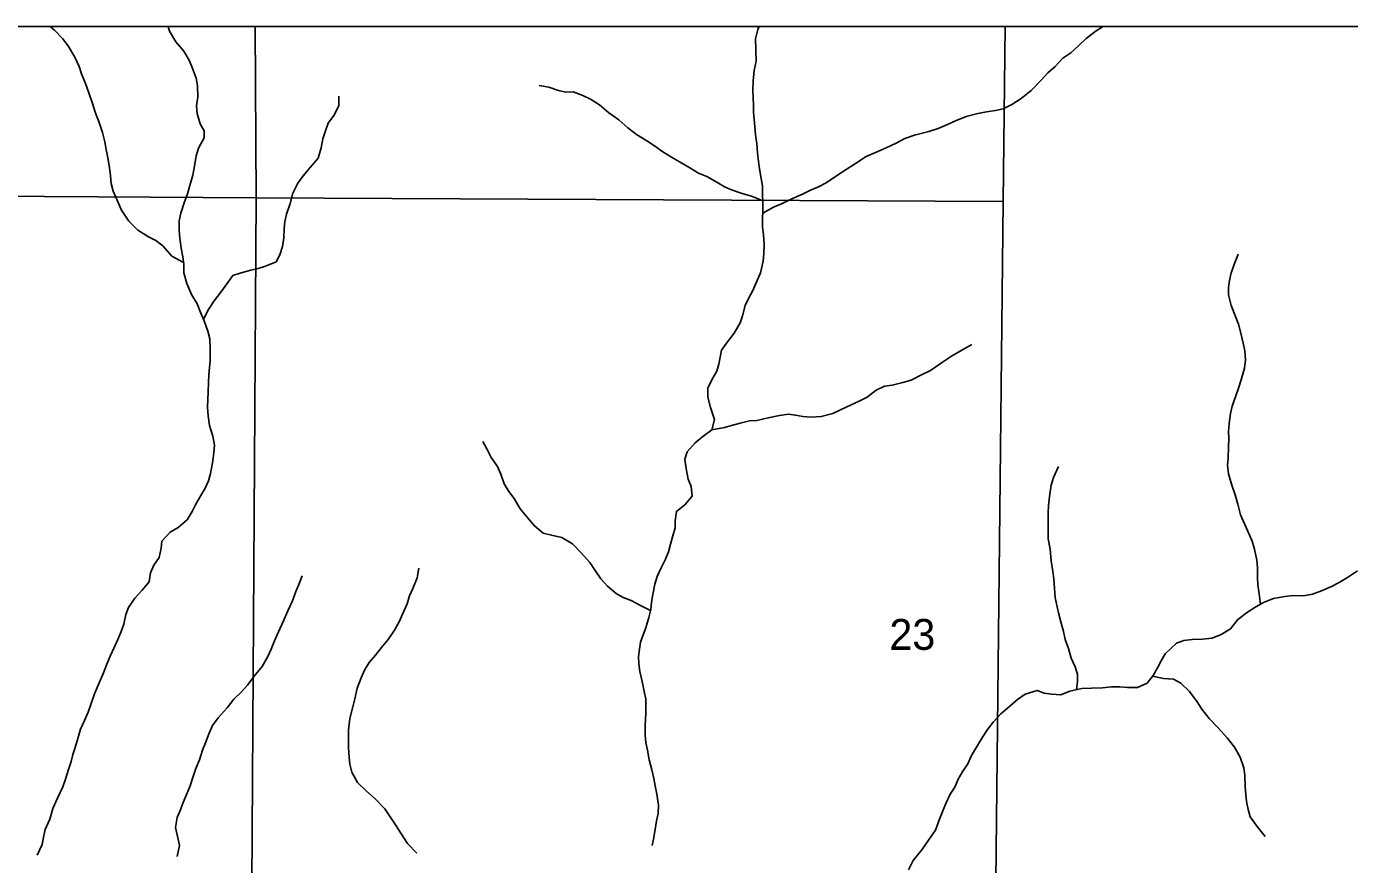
# Model space of a CAD drawing. Extents: x -10 to 158, y 8 to 33.
# Drawn here: x -6.322 to -4.528, y 13.985 to 15.122 of the extents above; entities that cross this region are included whole.
import ezdxf

# ---------------------------------------------------------------- set-up
doc = ezdxf.new("R2010")
doc.units = 0
for name, color, linetype in [('GM_X_Corporation', 7, 'Continuous'), ('GM_X_Minor_River', 7, 'Continuous'), ('GM_X_Section_Text', 7, 'Continuous')]:
    doc.layers.add(name, color=color, linetype=linetype)

msp = doc.modelspace()

# ---------------------------------------------------------------- linework, layer by layer
at = {"layer": 'GM_X_Corporation'}
for points in [[(-4.0034, 12.5894), (-3.9988, 12.8693), (-3.9975, 12.9799), (-3.993, 13.4391), (-3.9918, 13.5028), (-3.9936, 13.8697), (-3.9863, 14.2697), (-3.983, 14.8658), (-3.9828, 14.8868), (-3.9824, 15.1217), (-9.5644, 15.1217)], [(-4.0034, 12.5894), (-3.9988, 12.8693), (-3.9975, 12.9799), (-3.993, 13.4391), (-3.9918, 13.5028), (-3.9936, 13.8697), (-3.9863, 14.2697), (-3.983, 14.8658), (-3.9828, 14.8868), (-3.9824, 15.1217), (-7.9061, 15.1217)]]:
    msp.add_lwpolyline(points, dxfattribs=at)
for points in [[(-6.0117, 15.1217), (-7.016, 15.1217), (-7.0152, 14.8959), (-6.0105, 14.8894)], [(-4.9947, 15.1217), (-6.0117, 15.1217), (-6.0105, 14.8894), (-4.9975, 14.8842)], [(-7.0152, 14.8959), (-6.0105, 14.8894), (-6.0166, 13.8862), (-7.016, 13.8932)], [(-6.0105, 14.8894), (-4.9975, 14.8842), (-5.0085, 13.879), (-6.0166, 13.8862)]]:
    msp.add_lwpolyline(points, close=True, dxfattribs=at)
at = {"layer": 'GM_X_Minor_River'}
for points in [[(-6.3072, 13.9983), (-6.3006, 14.0124), (-6.2988, 14.0226), (-6.2962, 14.0329), (-6.2902, 14.0469), (-6.2858, 14.0614), (-6.2795, 14.0755), (-6.2724, 14.0907), (-6.2687, 14.1013), (-6.2653, 14.1127), (-6.2613, 14.1253), (-6.259, 14.1348), (-6.2557, 14.1443), (-6.252, 14.1564), (-6.2483, 14.169), (-6.2431, 14.1808), (-6.2383, 14.1922), (-6.2342, 14.2036), (-6.2297, 14.2169), (-6.223, 14.2317), (-6.2171, 14.2454), (-6.2126, 14.2572), (-6.2081, 14.2679), (-6.2022, 14.2804), (-6.1977, 14.2907), (-6.1932, 14.3013), (-6.1899, 14.3112), (-6.187, 14.3242), (-6.1832, 14.334), (-6.1746, 14.3466), (-6.1649, 14.3573), (-6.1555, 14.3687), (-6.1537, 14.3809), (-6.1492, 14.3912), (-6.1417, 14.4015), (-6.1391, 14.4144), (-6.1381, 14.4239), (-6.1268, 14.4361), (-6.1159, 14.4426), (-6.1038, 14.4529), (-6.0971, 14.4643), (-6.0923, 14.4739), (-6.0851, 14.4857), (-6.0795, 14.4956), (-6.0747, 14.5058), (-6.0721, 14.5157), (-6.0696, 14.5301), (-6.0678, 14.5434), (-6.0667, 14.5541), (-6.0691, 14.5662), (-6.0737, 14.5806), (-6.0753, 14.5938), (-6.0761, 14.6056), (-6.0758, 14.6159), (-6.0755, 14.6265), (-6.0749, 14.639), (-6.0746, 14.6489), (-6.0735, 14.6591), (-6.0728, 14.669), (-6.0725, 14.6838), (-6.073, 14.6982), (-6.0757, 14.7088), (-6.0807, 14.7224), (-6.0854, 14.733), (-6.0904, 14.7455), (-6.098, 14.7584), (-6.1042, 14.7731), (-6.1084, 14.7875), (-6.1085, 14.7993), (-6.1097, 14.8095), (-6.1121, 14.8213), (-6.1137, 14.8345), (-6.1145, 14.8452), (-6.1146, 14.8581), (-6.1124, 14.8687), (-6.108, 14.8828), (-6.1035, 14.8949), (-6.1002, 14.906), (-6.0961, 14.92), (-6.0936, 14.9348), (-6.0918, 14.9462), (-6.0884, 14.9569), (-6.081, 14.9706), (-6.0807, 14.9801), (-6.086, 14.9899), (-6.0903, 15.0039), (-6.0911, 15.0142), (-6.0893, 15.0259), (-6.0898, 15.0419), (-6.0917, 15.0517), (-6.0971, 15.0661), (-6.101, 15.0759), (-6.1083, 15.0884), (-6.119, 15.1009), (-6.1278, 15.1152), (-6.1294, 15.1217)], [(-6.1088, 14.8016), (-6.1245, 14.8102), (-6.1367, 14.8241), (-6.1462, 14.8317), (-6.1565, 14.8365), (-6.1709, 14.8456), (-6.1831, 14.8576), (-6.1931, 14.8727), (-6.1977, 14.8841), (-6.2042, 14.8985), (-6.2069, 14.9087), (-6.2078, 14.9193), (-6.209, 14.9307), (-6.2113, 14.9436), (-6.2137, 14.9549), (-6.2157, 14.9655), (-6.2188, 14.978), (-6.223, 14.9917), (-6.2284, 15.0057), (-6.2323, 15.0174), (-6.2369, 15.0303), (-6.2416, 15.0443), (-6.247, 15.0576), (-6.2504, 15.0674), (-6.2562, 15.0803), (-6.2646, 15.0946), (-6.2723, 15.1048), (-6.2837, 15.1165), (-6.2896, 15.1217)], [(-5.4735, 14.0113), (-5.4714, 14.0199), (-5.4692, 14.0328), (-5.4674, 14.0446), (-5.4652, 14.0548), (-5.4646, 14.0658), (-5.4669, 14.0806), (-5.4693, 14.092), (-5.4709, 14.1022), (-5.474, 14.114), (-5.4775, 14.1272), (-5.4798, 14.1405), (-5.4818, 14.1511), (-5.483, 14.1609), (-5.4827, 14.1738), (-5.4821, 14.1905), (-5.4818, 14.2), (-5.4818, 14.2103), (-5.4842, 14.2201), (-5.4869, 14.2334), (-5.49, 14.247), (-5.4913, 14.2576), (-5.4921, 14.2675), (-5.4906, 14.2774), (-5.4892, 14.2869), (-5.4855, 14.2967), (-5.4818, 14.3062), (-5.4781, 14.3203), (-5.4751, 14.3313), (-5.4741, 14.3412), (-5.4726, 14.3515), (-5.4697, 14.3655), (-5.4664, 14.3758), (-5.4623, 14.3857), (-5.4552, 14.3994), (-5.4514, 14.4096), (-5.4485, 14.4199), (-5.4452, 14.4313), (-5.4422, 14.4419), (-5.4423, 14.4514), (-5.4405, 14.4643), (-5.4292, 14.4731), (-5.4191, 14.485), (-5.4207, 14.4982), (-5.4245, 14.5081), (-5.4273, 14.5225), (-5.4289, 14.535), (-5.4259, 14.5452), (-5.415, 14.5571), (-5.4049, 14.5659), (-5.3924, 14.575), (-5.3887, 14.5887), (-5.3942, 14.605), (-5.398, 14.619), (-5.3981, 14.6312), (-5.3922, 14.6437), (-5.3858, 14.6544), (-5.3828, 14.6639), (-5.3792, 14.6829), (-5.3728, 14.6924), (-5.3623, 14.7061), (-5.3541, 14.7198), (-5.3507, 14.7294), (-5.3471, 14.7434), (-5.3426, 14.7529), (-5.3374, 14.7628), (-5.3325, 14.7742), (-5.3266, 14.7879), (-5.3229, 14.8035), (-5.3218, 14.8138), (-5.3215, 14.8259), (-5.3224, 14.8392), (-5.3236, 14.8502), (-5.3237, 14.8608), (-5.3234, 14.8714), (-5.3236, 14.9056), (-5.3256, 14.9158), (-5.3279, 14.9287), (-5.3291, 14.9386), (-5.3307, 14.9503), (-5.3316, 14.9625), (-5.3335, 14.9753), (-5.3344, 14.9856), (-5.3352, 14.9954), (-5.336, 15.0057), (-5.3361, 15.0152), (-5.3365, 15.0254), (-5.337, 15.0353), (-5.3363, 15.0482), (-5.3349, 15.0622), (-5.3323, 15.0748), (-5.3333, 15.1051), (-5.33, 15.1177), (-5.3282, 15.1217)], [(-5.3234, 14.8688), (-5.309, 14.8768), (-5.2969, 14.8819), (-5.283, 14.8884), (-5.2694, 14.8942), (-5.2585, 14.8996), (-5.2479, 14.9042), (-5.2373, 14.9096), (-5.226, 14.9172), (-5.2102, 14.9276), (-5.1989, 14.9352), (-5.1831, 14.9452), (-5.1706, 14.951), (-5.1563, 14.9571), (-5.1427, 14.9637), (-5.1307, 14.9698), (-5.1178, 14.9744), (-5.0982, 14.9795), (-5.0857, 14.9834), (-5.0729, 14.9888), (-5.0619, 14.9938), (-5.0476, 14.9996), (-5.0317, 15.0038), (-5.02, 15.0058), (-5.0079, 15.0078), (-4.9977, 15.0101), (-4.9856, 15.0159), (-4.9732, 15.0239), (-4.9593, 15.035), (-4.9458, 15.0488), (-4.9367, 15.0587), (-4.927, 15.0675), (-4.9168, 15.0786), (-4.9059, 15.0858), (-4.895, 15.0961), (-4.8848, 15.1053), (-4.8713, 15.1157), (-4.862, 15.1217)], [(-5.3235, 14.8851), (-5.3375, 14.8911), (-5.3515, 14.8952), (-5.3656, 14.9), (-5.3751, 14.9045), (-5.3857, 14.9105), (-5.3994, 14.9184), (-5.4104, 14.9229), (-5.4225, 14.93), (-5.4362, 14.9383), (-5.4472, 14.9443), (-5.459, 14.9518), (-5.4701, 14.9597), (-5.4807, 14.9668), (-5.4944, 14.9751), (-5.5062, 14.9841), (-5.5187, 14.995), (-5.5321, 15.0044), (-5.5446, 15.0154), (-5.5572, 15.0233), (-5.5674, 15.0281), (-5.5803, 15.033), (-5.5905, 15.0325), (-5.6004, 15.0351), (-5.6133, 15.0396), (-5.6266, 15.0418)], [(-6.0819, 14.725), (-6.0748, 14.738), (-6.0673, 14.7495), (-6.0583, 14.7613), (-6.0489, 14.7746), (-6.0418, 14.7842), (-6.0305, 14.7876), (-6.0176, 14.7911), (-6.0078, 14.7935), (-5.9976, 14.7966), (-5.9833, 14.8027), (-5.9781, 14.8123), (-5.9747, 14.8233), (-5.9729, 14.8351), (-5.9722, 14.848), (-5.9716, 14.8575), (-5.969, 14.867), (-5.9642, 14.8818), (-5.9608, 14.8955), (-5.9538, 14.9092), (-5.9466, 14.9191), (-5.9372, 14.9305), (-5.9264, 14.9431), (-5.9223, 14.9572), (-5.9197, 14.9693), (-5.9164, 14.9804), (-5.9127, 14.9906), (-5.9052, 15.0009), (-5.8981, 15.0139), (-5.8982, 15.0272)], [(-4.6487, 14.3382), (-4.6506, 14.3524), (-4.6522, 14.3646), (-4.6527, 14.3744), (-4.6528, 14.3881), (-4.6536, 14.398), (-4.6567, 14.4131), (-4.6598, 14.4237), (-4.6664, 14.4385), (-4.6756, 14.4597), (-4.6791, 14.4741), (-4.683, 14.4869), (-4.6876, 14.4998), (-4.6919, 14.515), (-4.6931, 14.5267), (-4.6924, 14.5366), (-4.6921, 14.5518), (-4.6914, 14.5631), (-4.6919, 14.5726), (-4.6912, 14.5833), (-4.6894, 14.5969), (-4.6868, 14.6068), (-4.682, 14.6209), (-4.6783, 14.6315), (-4.675, 14.6425), (-4.6702, 14.6585), (-4.6687, 14.6699), (-4.6699, 14.6817), (-4.6723, 14.6923), (-4.675, 14.704), (-4.6785, 14.718), (-4.6824, 14.7286), (-4.6882, 14.7434), (-4.692, 14.7578), (-4.6921, 14.7677), (-4.6907, 14.7772), (-4.6885, 14.7878), (-4.6844, 14.7992), (-4.6788, 14.8129)], [(-5.3924, 14.575), (-5.3754, 14.5778), (-5.3656, 14.5809), (-5.3539, 14.584), (-5.3414, 14.5871), (-5.3316, 14.5876), (-5.3161, 14.5911), (-5.3006, 14.5942), (-5.2885, 14.5962), (-5.279, 14.5947), (-5.2692, 14.5929), (-5.2582, 14.5918), (-5.2442, 14.5927), (-5.2283, 14.5969), (-5.2182, 14.6019), (-5.2034, 14.6089), (-5.1917, 14.6143), (-5.1819, 14.6192), (-5.1695, 14.6284), (-5.1586, 14.6338), (-5.148, 14.6354), (-5.1333, 14.6389), (-5.1223, 14.642), (-5.1084, 14.6493), (-5.0959, 14.6551), (-5.0797, 14.6666), (-5.0661, 14.6758), (-5.0398, 14.6903)], [(-5.4755, 14.33), (-5.4892, 14.3366), (-5.5017, 14.3433), (-5.5127, 14.3474), (-5.5222, 14.353), (-5.534, 14.3628), (-5.5428, 14.373), (-5.5508, 14.3843), (-5.5581, 14.3949), (-5.5695, 14.4081), (-5.5813, 14.4202), (-5.5958, 14.4288), (-5.6098, 14.4322), (-5.6212, 14.4347), (-5.633, 14.4445), (-5.641, 14.4543), (-5.6524, 14.4679), (-5.6605, 14.4815), (-5.6677, 14.4914), (-5.6742, 14.5016), (-5.6785, 14.5148), (-5.6831, 14.525), (-5.6915, 14.5375), (-5.6977, 14.5492), (-5.703, 14.559)], [(-4.8982, 14.2224), (-4.8965, 14.2341), (-4.8966, 14.2435), (-4.8997, 14.2534), (-4.9051, 14.2651), (-4.909, 14.2784), (-4.9132, 14.2905), (-4.9156, 14.3015), (-4.9194, 14.3147), (-4.9218, 14.3249), (-4.9241, 14.3348), (-4.9269, 14.3477), (-4.9281, 14.3598), (-4.9289, 14.3727), (-4.9301, 14.3829), (-4.9325, 14.3973), (-4.9337, 14.4129), (-4.9365, 14.4269), (-4.9366, 14.4501), (-4.9364, 14.4622), (-4.936, 14.4724), (-4.9346, 14.4842), (-4.9325, 14.4998), (-4.9291, 14.5104), (-4.9224, 14.5249)], [(-5.7925, 14.0009), (-5.8052, 14.014), (-5.814, 14.028), (-5.8205, 14.0378), (-5.8285, 14.0503), (-5.8358, 14.0608), (-5.8491, 14.0744), (-5.8609, 14.085), (-5.8731, 14.0966), (-5.8808, 14.1106), (-5.8835, 14.1216), (-5.8844, 14.1311), (-5.8852, 14.1436), (-5.8853, 14.1554), (-5.885, 14.1675), (-5.8832, 14.1834), (-5.8792, 14.1994), (-5.8766, 14.21), (-5.8733, 14.2245), (-5.8681, 14.2386), (-5.8636, 14.2488), (-5.8569, 14.2595), (-5.8486, 14.2694), (-5.8404, 14.2797), (-5.8313, 14.2904), (-5.8227, 14.3033), (-5.816, 14.3155), (-5.8119, 14.325), (-5.8056, 14.3391), (-5.8026, 14.3497), (-5.7981, 14.3596), (-5.7922, 14.3741), (-5.7896, 14.3874)], [(-6.1173, 13.9961), (-6.1144, 14.0113), (-6.1163, 14.0215), (-6.1195, 14.0355), (-6.1173, 14.0492), (-6.1132, 14.0587), (-6.1091, 14.0697), (-6.1043, 14.0811), (-6.0998, 14.0922), (-6.0961, 14.1032), (-6.092, 14.1157), (-6.0872, 14.1275), (-6.0831, 14.1404), (-6.079, 14.1503), (-6.0742, 14.1636), (-6.0693, 14.1739), (-6.0618, 14.1842), (-6.0498, 14.1979), (-6.0404, 14.2098), (-6.0307, 14.2189), (-6.022, 14.2288), (-6.013, 14.2407), (-6.0022, 14.254), (-5.9947, 14.2673), (-5.9898, 14.2776), (-5.9854, 14.2886), (-5.9802, 14.3008), (-5.9734, 14.316), (-5.9675, 14.3293), (-5.9611, 14.343), (-5.9563, 14.3556), (-5.9526, 14.3651), (-5.9481, 14.3769)], [(-5.126, 13.9781), (-5.1193, 13.991), (-5.1076, 14.0055), (-5.0986, 14.0184), (-5.0893, 14.0318), (-5.0837, 14.047), (-5.0792, 14.0584), (-5.0751, 14.0683), (-5.0692, 14.0808), (-5.0632, 14.0904), (-5.0583, 14.101), (-5.052, 14.1121), (-5.0456, 14.122), (-5.0404, 14.1334), (-5.0322, 14.1467), (-5.0254, 14.1581), (-5.0187, 14.1684), (-5.0112, 14.1783), (-5.0007, 14.1898), (-4.9883, 14.2001), (-4.9781, 14.2093), (-4.9676, 14.2162), (-4.9513, 14.2216), (-4.9418, 14.2178), (-4.932, 14.2164), (-4.9191, 14.2157), (-4.907, 14.2203), (-4.8908, 14.2242), (-4.8775, 14.2247), (-4.8628, 14.2252), (-4.8507, 14.2264), (-4.8393, 14.2264), (-4.8287, 14.2254), (-4.8155, 14.2255), (-4.8023, 14.2312), (-4.794, 14.2415), (-4.7884, 14.2522), (-4.7832, 14.2617), (-4.778, 14.2712), (-4.7625, 14.2857), (-4.7524, 14.2892), (-4.7414, 14.2904), (-4.7274, 14.2909), (-4.7141, 14.2925), (-4.7017, 14.2975), (-4.6893, 14.3052), (-4.6791, 14.3177), (-4.666, 14.3277), (-4.655, 14.3346), (-4.6445, 14.3407), (-4.6309, 14.3461), (-4.6154, 14.3489), (-4.6037, 14.3501), (-4.5904, 14.3498), (-4.5783, 14.3521), (-4.5659, 14.3564), (-4.5523, 14.3622), (-4.5417, 14.3679), (-4.5308, 14.3748), (-4.5169, 14.3836)], [(-4.7948, 14.2406), (-4.78, 14.2378), (-4.7664, 14.2368), (-4.7565, 14.2315), (-4.7447, 14.2198), (-4.7344, 14.2059), (-4.7279, 14.196), (-4.7183, 14.1836), (-4.7065, 14.1711), (-4.6939, 14.1572), (-4.684, 14.1447), (-4.6763, 14.1311), (-4.6713, 14.1167), (-4.6697, 14.1065), (-4.6692, 14.0909), (-4.6684, 14.0803), (-4.6676, 14.0708), (-4.6652, 14.0599), (-4.6625, 14.05), (-4.6533, 14.0368), (-4.6423, 14.0236)]]:
    msp.add_lwpolyline(points, dxfattribs=at)

# ---------------------------------------------------------------- texts
at = {"layer": 'GM_X_Section_Text'}
msp.add_text('23', height=0.04186, rotation=0, dxfattribs=at).set_placement((-5.1518, 14.2765))

doc.saveas('drawing.dxf')
